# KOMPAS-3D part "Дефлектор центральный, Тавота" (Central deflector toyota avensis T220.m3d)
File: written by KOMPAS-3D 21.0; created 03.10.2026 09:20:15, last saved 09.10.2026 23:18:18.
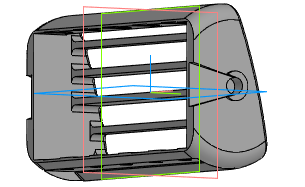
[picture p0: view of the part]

Document properties: Автор: 79164347213; Полное имя файла: C:\Users\79164\Desktop\Прокты\Тачка\Дефлектор _ Тавота.m3d

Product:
- Part/product: Дефлектор центральный  | designation Тавота
    Масса: 0.192719

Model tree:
1. Эскиз:1
2. Элемент выдавливания:1
     Расстояние 1 = 85
3. Эскиз:2  (with: Элемент выдавливания:1)
4. Элемент выдавливания:2
     Расстояние 2 = 14
5. Элемент выдавливания:3
     Расстояние 2 = 21
6. Элемент выдавливания:4
     Расстояние 1 = -15
7. Эскиз:3  (with: Элемент выдавливания:1)
8. Элемент выдавливания:5
     Расстояние 1 = 15
9. Элемент выдавливания:6
     Расстояние 1 = 15
10. Элемент выдавливания:7
     Расстояние 1 = 5.5
11. Скругление:3  (with: Элемент выдавливания:1)
     Радиус = 5
12. Скругление:2  (with: Элемент выдавливания:1)
     Радиус = 1
13. Эскиз:4  (with: Элемент выдавливания:4, Элемент выдавливания:1)
14. Элемент выдавливания:8  (with: Элемент выдавливания:3)
     Расстояние 1 = -3
15. Эскиз:5  (with: Элемент выдавливания:2, Элемент выдавливания:4, Элемент выдавливания:8)
16. Элемент выдавливания:9
     Расстояние 2 = 2
17. Фаска:2  (with: Элемент выдавливания:7)
     Угол = 45; Длина 1 = 2.9; Длина 2 = 2.9
18. Эскиз:6  (with: Элемент выдавливания:3, Элемент выдавливания:8)
19. Элемент выдавливания:10
     Расстояние 2 = 0.2
20. Эскиз:7  (with: Элемент выдавливания:2, Элемент выдавливания:7, Фаска:2)
21. Элемент выдавливания:11
     Расстояние 2 = 0.2
22. Эскиз:8  (with: Элемент выдавливания:1)
23. Элемент выдавливания:14
     Расстояние 2 = 3
24. Зеркальный массив:1
25. Экземпляр ( 1 )
26. Экземпляр ( 2 )  (with: Элемент выдавливания:14)
27. Эскиз:9  (with: Элемент выдавливания:1, Элемент выдавливания:14)
28. Элемент вращения:1
     Угол 2 = 9
29. Зеркальный массив:2  (with: Экземпляр ( 1 ), Экземпляр ( 2 ), Элемент вращения:1)
30. Фаска:5  (with: Элемент выдавливания:4)
     Угол = 45; Длина 1 = 3; Длина 2 = 3
31. Эскиз:10  (with: Элемент выдавливания:1, Элемент вращения:1, Скругление:3)
32. Элемент выдавливания:15
     Расстояние 1 = 1
33. Фаска:6  (with: Элемент выдавливания:5)
     Угол = 45; Длина 1 = 2; Длина 2 = 2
